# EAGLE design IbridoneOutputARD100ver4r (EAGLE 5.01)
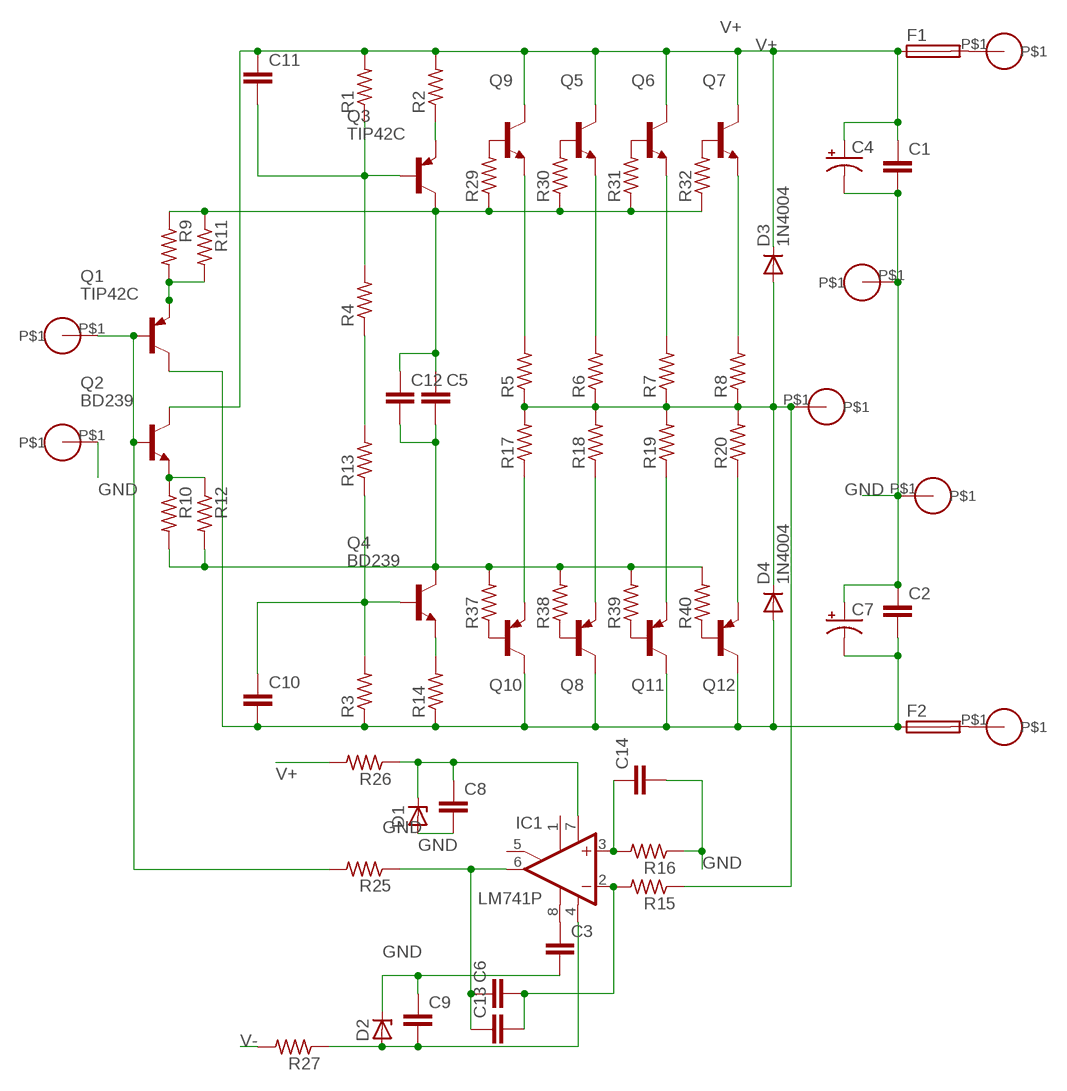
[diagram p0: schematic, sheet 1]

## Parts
C1  C-EU150-091X182  [C150-091X182]
C2  C-EU150-091X182  [C150-091X182]
C3  C-EU050-024X044  [C050-024X044]
C4  CPOL-USSANYO_H  [SANYO-OSCON_H]
C5  C-EU102-054X133  [C102-054X133]
C6  C-EU102-054X133  [C102-054X133]
C7  CPOL-USSANYO_H  [SANYO-OSCON_H]
C8  C-EU050-050X075  [C050-050X075]
C9  C-EU050-055X075  [C050-055X075]
C10  C-EU050-050X075  [C050-050X075]
C11  C-EU050-045X075  [C050-045X075]
C12  C-EU050-050X075  [C050-050X075]
C13  C-EU050-050X075  [C050-050X075]
C14  C-EU050-050X075  [C050-050X075]
D1  ZENER-DIODEDO34-7  [DO34Z7]
D2  ZENER-DIODEDO34-7  [DO34Z7]
D3  1N4004  [DO41-10]
D4  1N4004  [DO41-10]
F1  SH22,5A  [SH22,5A]
F2  SH22,5A  [SH22,5A]
IC1  LM741P  [DIL08]
IN+  FASTON  [FASTON]
IN-  FASTON  [FASTON]
OUT-  FASTON  [FASTON]
OUT-1  FASTON  [FASTON]
Q1  TIP42C  BD240  [TO220]
Q2  BD239  [TO220]
Q3  TIP42C  BD240  [TO220]
Q4  BD239  [TO220]
Q5  -NPN-TO218  [TO218]
Q6  -NPN-TO218  [TO218]
Q7  -NPN-TO218  [TO218]
Q8  -PNP-TO218  [TO218]
Q9  -NPN-TO218  [TO218]
Q10  -PNP-TO218  [TO218]
Q11  -PNP-TO218  [TO218]
Q12  -PNP-TO218  [TO218]
R1  R-US_0207/5V  [0207/5V]
R2  R-US_0207/5V  [0207/5V]
R3  R-US_0207/5V  [0207/5V]
R4  R-US_0411/12  [0411/12]
R5  R-US_0617/22  [0617/22]
R6  R-US_0617/22  [0617/22]
R7  R-US_0617/22  [0617/22]
R8  R-US_0617/22  [0617/22]
R9  R-US_0207/5V  [0207/5V]
R10  R-US_0207/5V  [0207/5V]
R11  R-US_0207/5V  [0207/5V]
R12  R-US_0207/5V  [0207/5V]
R13  R-US_0411/12  [0411/12]
R14  R-US_0207/5V  [0207/5V]
R15  R-US_0207/5V  [0207/5V]
R16  R-US_0207/5V  [0207/5V]
R17  R-US_0617/22  [0617/22]
R18  R-US_0617/22  [0617/22]
R19  R-US_0617/22  [0617/22]
R20  R-US_0617/22  [0617/22]
R25  R-US_0207/5V  [0207/5V]
R26  R-US_0207/5V  [0207/5V]
R27  R-US_0207/5V  [0207/5V]
R29  R-US_0207/10  [0207/10]
R30  R-US_0207/10  [0207/10]
R31  R-US_0207/10  [0207/10]
R32  R-US_0207/10  [0207/10]
R37  R-US_0207/10  [0207/10]
R38  R-US_0207/10  [0207/10]
R39  R-US_0207/10  [0207/10]
R40  R-US_0207/10  [0207/10]
U$2  FASTON  [FASTON]
V+  FASTON  [FASTON]
V-  FASTON  [FASTON]

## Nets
GND: C1.2 C2.1 C3.2 C4.- C7.+ C8.2 C9.1 C14.2 D1.A D2.C IN-.P$1 OUT-1.P$1 OUT-.P$1 R16.1
N$1: C6.2 C13.2 IC1.2(-IN) R15.2
N$2: C5.1 C12.1 Q3.2(C) R9.1 R11.1 R29.1 R30.1 R31.1 R32.1
N$3: C11.2 Q3.1(B) R1.1 R4.2
N$4: Q5.1(B) R30.2
N$5: Q3.3(E) R2.1
N$6: R4.1 R13.2
N$7: C5.2 C12.2 Q4.2(C) R10.2 R12.2 R37.2 R38.2 R39.2 R40.2
N$8: C10.1 Q4.1(B) R3.2 R13.1
N$9: Q9.3(E) R5.2
N$10: Q5.3(E) R6.2
N$11: Q6.3(E) R7.2
N$12: Q7.3(E) R8.2
N$13: Q6.1(B) R31.2
N$14: Q7.1(B) R32.2
N$15: Q8.1(B) R38.1
N$16: C6.1 C13.1 IC1.6(OUT) R25.1
N$17: Q10.1(B) R37.1
N$18: C14.1 IC1.3(+IN) R16.2
N$19: Q4.3(E) R14.2
N$20: C8.1 D1.C IC1.7(V+) R26.1
N$21: Q9.1(B) R29.2
N$22: Q11.1(B) R39.1
N$23: Q10.3(E) R17.1
N$24: Q8.3(E) R18.1
N$25: Q11.3(E) R19.1
N$26: Q12.3(E) R20.1
N$27: Q12.1(B) R40.1
N$28: C3.1 IC1.8(OPT)
N$29: F1.2 V+.P$1
N$30: F2.2 V-.P$1
N$31: IN+.P$1 Q1.1(B) Q2.1(B) R25.2
N$32: Q2.3(E) R10.1 R12.1
N$33: Q1.3(E) R9.2 R11.2
N$41: C9.2 D2.A IC1.4(V-) R27.1
OUT+: D3.A D4.C R5.1 R6.1 R7.1 R8.1 R15.1 R17.2 R18.2 R19.2 R20.2 U$2.P$1
V+: C1.1 C4.+ C11.1 D3.C F1.1 Q2.2(C) Q5.2(C) Q6.2(C) Q7.2(C) Q9.2(C) R1.2 R2.2 R26.2
V-: C2.2 C7.- C10.2 D4.A F2.1 Q1.2(C) Q8.2(C) Q10.2(C) Q11.2(C) Q12.2(C) R3.1 R14.1 R27.2
Unconnected: IC1.1(ON1) IC1.5(ON2)

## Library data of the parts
C1-C3 C5 C6 C8-C14 = rcl:C-EU: CAPACITOR, European symbol
C4 C7 = rcl:CPOL-US: POLARIZED CAPACITOR, American symbol
D1 D2 = diode:ZENER-DIODE: Z-Diode
D3 D4 = diode:1N4004: DIODE
F1 F2 = fuse:SH22,5A: FUSE HOLDER
IC1 = linear:*741: OP AMP
IN+ IN- OUT- OUT-1 U$2 V+ V- = mylib2:FASTON
Q1 Q3 = transistor-pnp:BD240: PNP Transistor
Q2 Q4 = transistor:BD239: NPN TRANSISTOR Source: http://www.fairchildsemi.com/ds/BD/BD239C.pdf
Q5-Q7 Q9 = transistor:*-NPN-: NPN Transistror BF959 corrected 2008.03.06
Q8 Q10-Q12 = transistor:*-PNP-: PNP Transistror
R1-R20 R25-R27 R29-R32 R37-R40 = rcl:R-US_: RESISTOR, American symbol

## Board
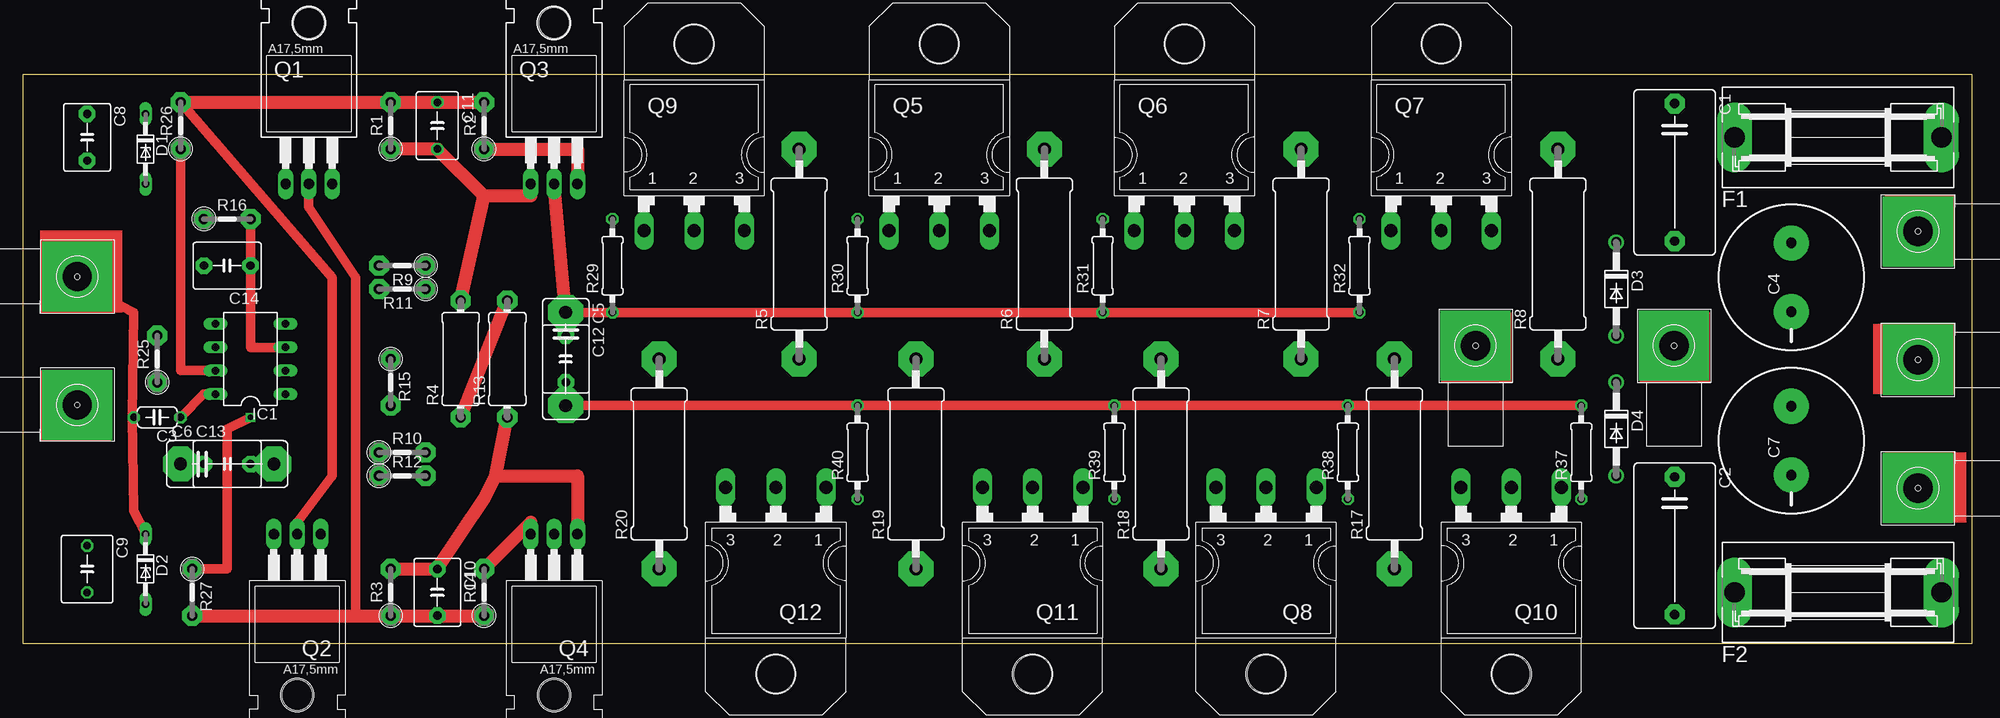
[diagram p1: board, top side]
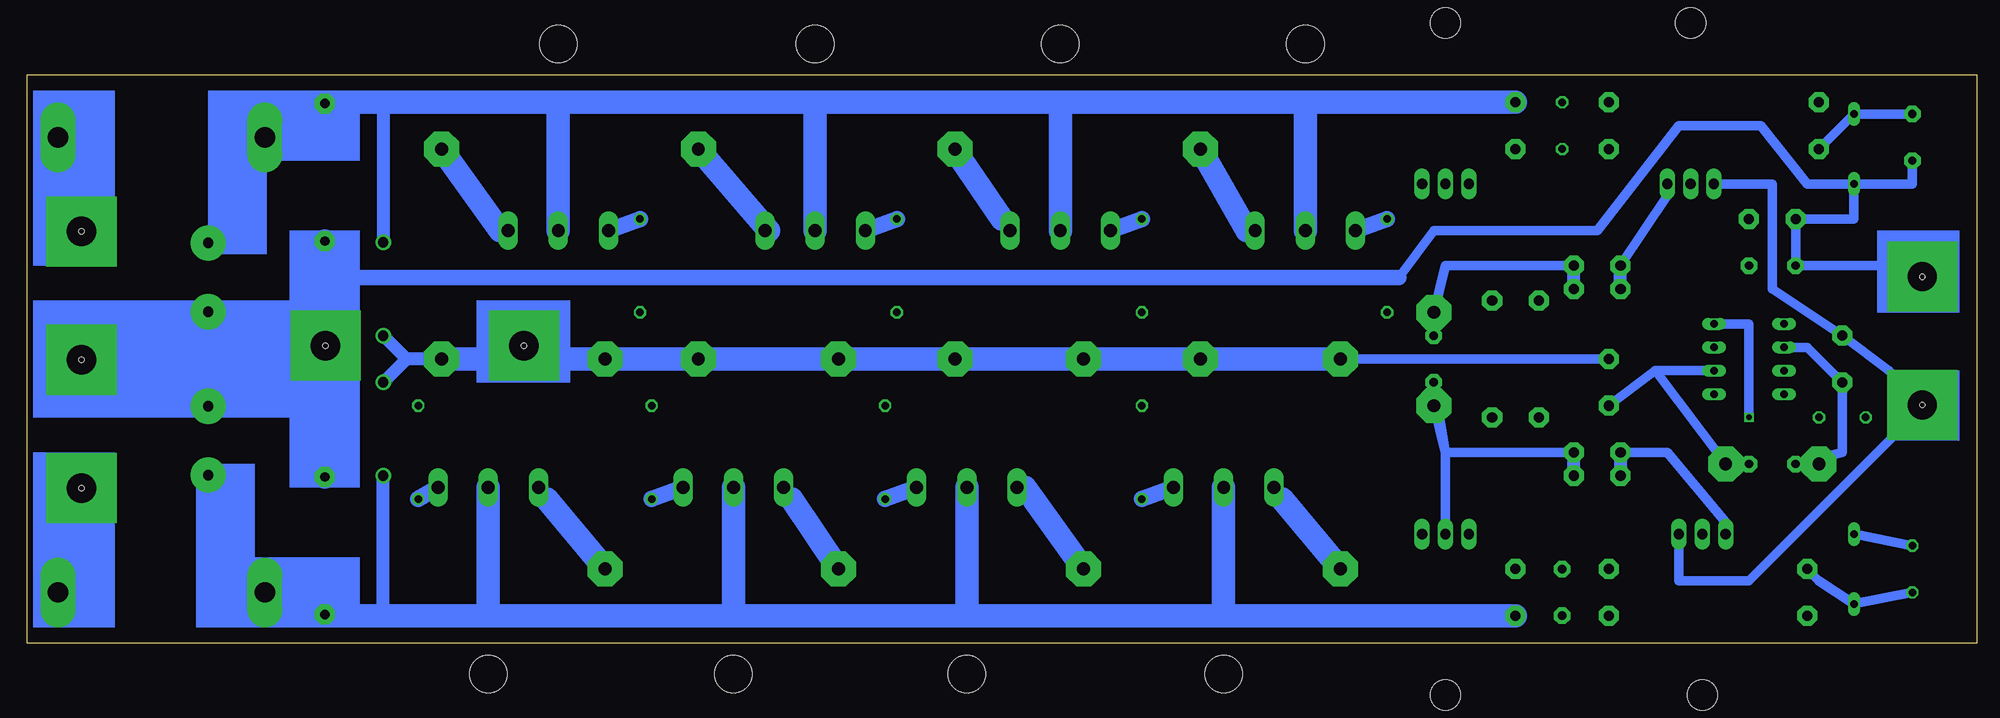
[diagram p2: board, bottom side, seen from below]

Size 212.07 x 61.9 mm. Coordinates in mm from the lower left corner, seen from the top.
Outline: 0,0 212.07,0 212.07,61.9 0,61.9 0,0
Copper layers (1*16): Top 0.035mm / dielectric 1.5mm / Bottom 0.035mm
Design rules "default": minimum track width 10mil, minimum drill 24mil, track to track 8mil, track to pad 8mil, pad to pad 8mil, via to via 8mil, smd to smd 8mil, copper to edge 40mil, drill to drill 8mil, minimum pad ring 10mil, minimum via ring 8mil, stop-mask expansion 4mil, vias tented up to drill 0mil, thermal gap 10mil

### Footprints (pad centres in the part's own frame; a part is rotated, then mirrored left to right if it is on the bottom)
C150-091X182 = drill 1.016 pad 2.184 octagon: 1 -7.493,0; 2 7.493,0
C050-024X044 = drill 0.813 octagon: 1 -2.54,0; 2 2.54,0
SANYO-OSCON_H = drill 1.1 pad 3.81 round: + 3.75,0; - -3.75,0
C102-054X133 = drill 1.4 pad 3.81 octagon: 1 -5.08,0; 2 5.08,0
C050-050X075 = drill 0.9 pad 1.778 octagon: 1 -2.54,0; 2 2.54,0
C050-055X075 = drill 0.813 octagon: 1 -2.54,0; 2 2.54,0
C050-045X075 = drill 0.813 octagon: 1 -2.54,0; 2 2.54,0
DO34Z7 = drill 0.813 long: A 3.81,0; C -3.81,0
DO41-10 = drill 1.118 round: A 5.08,0; C -5.08,0
SH22,5A = drill 2.2 pad 3.81 long: 1 -11.252,0; 2 11.252,0
DIL08 = drill 0.813 long: 1 -3.81,-3.81; 2 -1.27,-3.81; 3 1.27,-3.81; 4 3.81,-3.81; 5 3.81,3.81; 6 1.27,3.81; 7 -1.27,3.81; 8 -3.81,3.81
FASTON = drill 3.2 pad 7.62 square: P$1 -5,-4 | hole 0.6: -5,-4
TO220 = drill 1.118 long: 1 -2.54,-6.35; 2 0,-6.35; 3 2.54,-6.35 | hole 3.302: 0,11.176
TO218 = drill 1.397 long: 1 -5.461,-10.16; 2 0,-10.16; 3 5.461,-10.16 | hole 4.115: 0,10.16
0207/5V = drill 1.1 pad 2.184 octagon: 1 -2.54,0; 2 2.54,0
0411/12 = drill 1.1 pad 2.184 octagon: 1 -6.35,0; 2 6.35,0
0617/22 = drill 1.4 pad 3.81 octagon: 1 -11.43,0; 2 11.43,0
0207/10 = drill 0.813 octagon: 1 -5.08,0; 2 5.08,0

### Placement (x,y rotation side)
C1  179.7,51.27 270 top
C2  179.7,10.63 270 top
C3  14.6,24.6 180 top
C4  192.4,39.84 90 top
C5  59.05,30.95 270 top
C6  22.22,19.52 0 top
C7  192.4,22.06 90 top
C8  6.98,55.08 270 top
C9  6.98,8.09 270 top
C10  45.08,5.55 270 top
C11  45.08,56.35 270 top
C12  59.05,30.95 270 top
C13  22.22,19.52 0 top
C14  22.22,41.11 180 top
D1  13.33,53.81 270 top
D2  13.33,8.09 270 top
D3  173.35,38.57 270 top
D4  173.35,23.33 270 top
F1  197.48,55.08 0 top
F2  197.48,5.55 0 top
IC1  24.76,30.95 90 top
IN+  1.9,30.95 90 top
IN-  174.62,28.41 180 top
OUT-  1.9,44.92 90 top
OUT-1  210.18,25.87 270 top
Q1  31.11,56.35 0 top
Q2  29.84,5.55 180 top
Q3  57.78,56.35 0 top
Q4  57.78,5.55 180 top
Q5  99.69,55.08 0 top
Q6  126.36,55.08 0 top
Q7  154.3,55.08 0 top
Q8  135.25,6.82 180 top
Q9  73.02,55.08 0 top
Q10  161.92,6.82 180 top
Q11  109.85,6.82 180 top
Q12  81.91,6.82 180 top
R1  40,56.35 90 top
R2  50.16,56.35 90 top
R3  40,5.55 90 top
R4  47.62,30.95 90 top
R5  84.45,42.38 90 top
R6  111.12,42.38 90 top
R7  139.06,42.38 90 top
R8  167,42.38 90 top
R9  41.27,41.11 180 top
R10  41.27,20.79 0 top
R11  41.27,38.57 180 top
R12  41.27,18.25 0 top
R13  52.7,30.95 90 top
R14  50.16,5.55 90 top
R15  40,28.41 270 top
R16  22.22,46.19 0 top
R17  149.22,19.52 90 top
R18  123.82,19.52 90 top
R19  97.15,19.52 90 top
R20  69.21,19.52 90 top
R25  14.6,30.95 90 top
R26  17.14,56.35 90 top
R27  18.41,5.55 270 top
R29  64.13,41.11 90 top
R30  90.8,41.11 90 top
R31  117.47,41.11 90 top
R32  145.41,41.11 90 top
R37  169.54,20.79 90 top
R38  144.14,20.79 90 top
R39  118.74,20.79 90 top
R40  90.8,20.79 90 top
U$2  153.03,28.41 180 top
V+  210.18,39.84 270 top
V-  210.18,11.9 270 top

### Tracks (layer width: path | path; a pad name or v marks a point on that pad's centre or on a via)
GND
  Top 0.254: 11.9,24.62 C3.2
  Top 1.016: D2.C 12.06,14.44 11.9,24.62 12.06,36.03 9.52,37.3 OUT-.P$1
  Bottom 0.254: 189.86,25.87 C7.+ | 189.86,30.91 189.86,30.95
  Bottom 1.016: 182.24,30.95 IN-.P$1 | OUT-1.P$1 191.13,30.95 | D1.A 13.33,46.19 R16.1 C14.2 9.52,41.11 OUT-.P$1 | D2.C C9.1 | 62.86,39.84 59.05,44.92 41.27,44.92 32.38,56.35 23.49,56.35 18.41,50 D1.A | C8.2 6.98,50 D1.A
  Bottom 1.676: 62.86,39.84 177.16,39.84
  Bottom 2.54: 182.24,30.95 C2.1 | 182.24,30.95 177.16,39.84 C1.2 | 182.24,30.95 189.86,30.91 | 189.86,30.91 OUT-1.P$1 | IN-.P$1 191.13,30.95 | 189.86,30.91 189.86,25.87 | 189.86,30.95 C4.-
N$1
  Bottom 0.254: C13.2 C6.2
  Bottom 1.016: 34.92,29.68 IC1.2 | 34.92,29.68 R15.2 | C6.2 34.92,29.68
N$2
  Top 0.254: C5.1 C12.1 C5.1
  Top 1.016: C5.1 R29.1 R30.1 R31.1 R32.1
  Top 1.422: C5.1 Q3.2
  Bottom 0.254: C5.1 C12.1
  Bottom 1.016: R9.1 57.78,41.11 C5.1
  Bottom 1.422: R11.1 R9.1
N$3
  Top 0.254: 55.24,48.73 Q3.1
  Top 1.422: R4.2 50.16,48.73 | 50.16,48.73 C11.2 R1.1 | 50.16,48.73 55.24,48.73
N$4
  Bottom 1.778: Q5.1 R30.2
N$5
  Top 1.422: R2.1 60.32,53.81 Q3.3
N$6
  Top 1.422: R4.1 R13.2
N$7
  Top 0.254: C5.2 C12.2
  Top 1.016: R37.2 R38.2 R39.2 R40.2 C5.2
  Bottom 0.254: Q4.2 57.78,10.63
  Bottom 1.016: R10.2 57.78,20.79 | 57.78,20.79 C5.2 | 57.78,20.79 C12.2 | 57.78,20.79 Q4.2
  Bottom 1.422: R12.2 R10.2
N$8
  Top 1.422: R3.2 C10.1 50.16,15.71 51.43,18.25 | 51.43,18.25 R13.1 | 51.43,18.25 60.32,18.25 Q4.1
N$9  (via drill 0.6)
  Bottom 1.778: Q9.3 79.37,44.92
  Bottom 2.54: 79.37,44.92 R5.2
  other vias: 84.45,53.81
N$10  (via drill 0.6)
  Bottom 1.778: Q5.3 106.04,46.19
  Bottom 2.54: 106.04,46.19 110.47,52.72 R6.2
  other vias: 111.12,53.81
N$11
  Bottom 1.778: Q6.3 131.44,44.92
  Bottom 2.54: 131.44,44.92 R7.2
N$12
  Bottom 1.778: Q7.3 160.65,44.92
  Bottom 2.54: 160.65,44.92 R8.2
N$13
  Bottom 1.778: Q6.1 R31.2
N$14
  Bottom 1.778: Q7.1 R32.2
N$15
  Bottom 1.778: Q8.1 R38.1
N$16
  Bottom 1.016: IC1.6 18.41,32.22 R25.1 14.6,20.79 C13.1 C6.1
N$17
  Bottom 1.778: Q10.1 R37.1
N$18
  Top 0.254: 24.76,43.65 C14.1
  Top 1.016: R16.2 24.76,43.65 24.76,32.22 IC1.3
N$19
  Top 0.254: 55.24,13.17 Q4.3
  Top 1.422: R14.2 55.24,13.17
N$20
  Top 1.016: IC1.7 17.14,29.68 R26.1
  Bottom 1.016: C8.1 D1.C R26.1
N$21
  Bottom 1.778: R29.2 Q9.1
N$22
  Bottom 1.778: Q11.1 R39.1
N$23
  Bottom 1.778: 155.57,15.71 Q10.3
  Bottom 2.54: R17.1 155.57,15.71
N$24  (via drill 0.6)
  Bottom 1.778: 128.9,15.71 Q8.3
  Bottom 2.54: R18.1 128.9,15.71
  other vias: 123.82,8.09
N$25
  Bottom 1.778: 103.5,16.98 Q11.3
  Bottom 2.54: R19.1 103.5,16.98
N$26
  Bottom 1.778: 75.56,15.71 Q12.3
  Bottom 2.54: R20.1 75.56,15.71
N$27
  Bottom 1.778: Q12.1 R40.1
N$28
  Top 1.016: C3.1 19.68,27.14 IC1.8
N$29
  Bottom 2.54: F1.2 206.37,53.81 206.37,47.46 V+.P$1
N$30
  Bottom 0.254: F2.2 208.91,5.55
  Bottom 2.54: 208.91,5.55 208.91,10.63 V-.P$1
N$31
  Bottom 1.016: Q2.1 32.38,6.82 24.76,6.82 8.25,23.33 IN+.P$1 9.52,29.68 R25.2 22.22,38.57 22.22,50 Q1.1
N$32
  Bottom 0.254: Q2.3 27.3,13.17
  Bottom 1.016: 27.3,13.17 33.65,20.79 R10.1
  Bottom 1.422: R10.1 R12.1
N$33
  Bottom 0.254: 33.65,48.73 Q1.3
  Bottom 1.016: R9.2 33.65,48.73
  Bottom 1.422: R11.2 R9.2
N$41  (via drill 0.6)
  Top 1.016: R27.1 22.22,8.09 22.22,23.33 v24.76,24.6
  Bottom 1.016: C9.2 D2.A 17.14,6.82 R27.1 | IC1.4 24.76,34.76 v24.76,24.6
OUT+
  Bottom 1.016: R15.1 R20.2
  Bottom 1.422: 170.81,30.95 D3.A | 170.81,30.95 D4.C | R8.1 170.81,30.95
  Bottom 2.54: 160.65,30.95 R8.1 | 160.65,30.95 R17.2 R7.1 R18.2 R6.1 R19.2 R5.1 R20.2 | 160.65,30.95 U$2.P$1
V+
  Top 0.254: Q2.2 29.84,13.17
  Top 1.016: 29.84,13.17 33.65,18.25 33.65,39.84 R26.2
  Top 1.422: R26.2 R1.2 C11.1 R2.2
  Bottom 0.254: 175.89,58.89 177.16,58.89 C1.1 | 189.86,43.65 C4.+
  Bottom 1.422: 173.35,58.89 D3.C
  Bottom 2.54: 173.35,58.89 175.89,58.89 | R2.2 73.02,58.89 | 73.02,58.89 Q9.2 | 73.02,58.89 99.69,58.89 | 99.69,58.89 Q5.2 | 99.69,58.89 126.36,58.89 | 126.36,58.89 Q6.2 | 126.36,58.89 154.3,58.89 | 154.3,58.89 Q7.2 | 189.86,43.65 189.86,55.08 F1.1 183.51,58.89 173.35,58.89 | 154.3,58.89 173.35,58.89
V-
  Top 1.016: Q1.2 31.11,47.46 36.19,39.84 36.19,3.01 R3.1
  Top 1.422: R14.1 C10.2 R3.1 R27.2
  Bottom 0.254: 192.4,18.25 C7.- | F2.1 184.78,8.09
  Bottom 1.422: 173.35,3.01 D4.A
  Bottom 2.54: 173.35,3.01 177.16,3.01 C2.2 | R14.1 81.91,3.01 | 81.91,3.01 Q12.2 | 81.91,3.01 109.85,3.01 | 109.85,3.01 Q11.2 | 135.25,3.01 Q8.2 | 109.85,3.01 135.25,3.01 | 135.25,3.01 161.92,3.01 | 161.92,3.01 Q10.2 | 192.4,18.25 192.4,8.09 184.78,8.09 | 161.92,3.01 173.35,3.01 | 173.35,3.01 179.7,3.01 F2.1
(copper drawn outside any net)
  shapes: Bottom area x17, Top area x7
